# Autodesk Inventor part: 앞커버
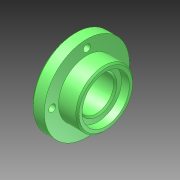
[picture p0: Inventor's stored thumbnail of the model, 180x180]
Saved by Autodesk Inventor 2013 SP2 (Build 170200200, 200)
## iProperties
Created: 2025-04
Part Number: 앞커버
Material: Generic
Document SubType Name: Modeling
Designer: 601
Density: 1 g/cm^3
Author: 601
변환 표준: STEP AP214IS
전처리기: Build: 200, Release: 2013 SP2 Update 6 - Date: Thu 07/17/2014
전송 단위: 밀리미터
불확실성: 0.01
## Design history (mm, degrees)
node "앞커버1"
node "솔리드1"
node "기준1"
